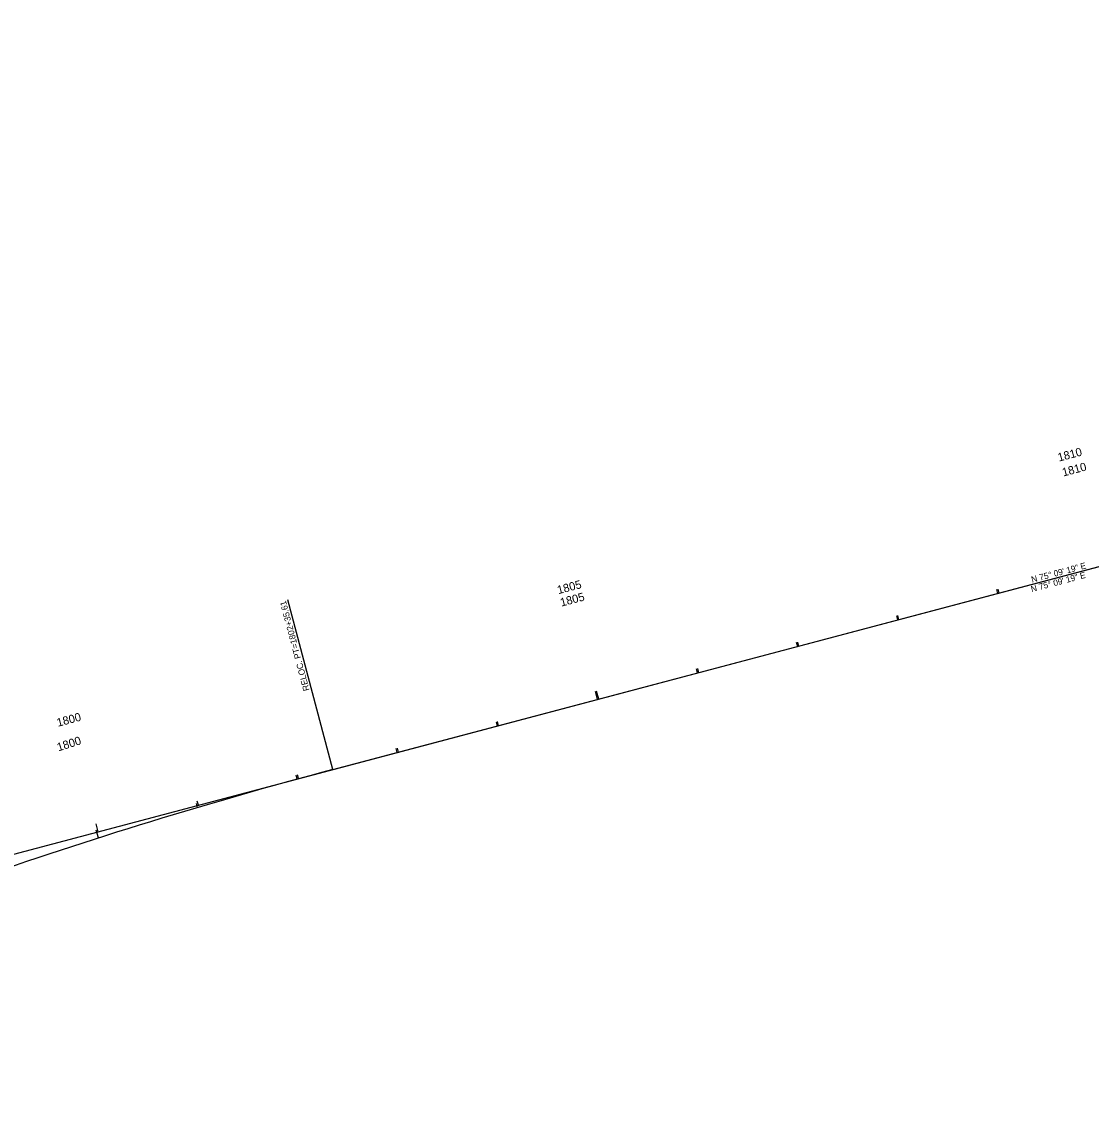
# Model space of a CAD drawing. Extents: x 2106154 to 2121963, y 864504 to 868517.
# Drawn here: x 2111052 to 2112084, y 867153 to 868210 of the extents above; entities that cross this region are included whole.
import ezdxf

# ---------------------------------------------------------------- set-up
doc = ezdxf.new("R2010")
doc.units = 0
for name, color, linetype in [('RD_HC_CL_Rel', 7, 'Continuous'), ('RD_HC_Data_Tic_Rel', 7, 'Continuous'), ('RD_HC_TX_Rel_Sta50', 7, 'Continuous'), ('RD_PD_EarthShd', 7, 'Continuous'), ('RD_PD_EOP', 7, 'Continuous'), ('RD_PD_Final_LnLine', 7, 'Continuous'), ('RD_Sketch1', 7, 'Continuous'), ('RD_Sketch10', 7, 'Continuous')]:
    doc.layers.add(name, color=color, linetype=linetype)

msp = doc.modelspace()

# ---------------------------------------------------------------- linework, layer by layer
at = {"layer": 'RD_HC_Data_Tic_Rel'}
msp.add_line((2111352, 867487.6), (2112776.4, 867865.1), dxfattribs=at)
msp.add_arc((2112556.1, 862944.4), 4700, 104.8448, 109.3083, dxfattribs=at)
at = {"layer": 'RD_HC_TX_Rel_Sta50'}
msp.add_line((2111352, 867487.6), (2111308.5, 867651.6), dxfattribs=at)
at = {"layer": 'RD_PD_EarthShd'}
for p, q in [((2111995.4, 867658.1), (2111994.4, 867662)), ((2111898.7, 867632.5), (2111897.7, 867636.3)), ((2111802.1, 867606.9), (2111801.1, 867610.7)), ((2111705.4, 867581.2), (2111704.4, 867585.1)), ((2111608.8, 867555.6), (2111606.7, 867563.4)), ((2111512.1, 867530), (2111511.1, 867533.9)), ((2111415.4, 867504.4), (2111414.4, 867508.2)), ((2111318.8, 867478.8), (2111317.7, 867482.6)), ((2111222.1, 867453.1), (2111221.1, 867457)), ((2111125.4, 867427.5), (2111123.4, 867435.3))]:
    msp.add_line(p, q, dxfattribs=at)
at = {"layer": 'RD_PD_EOP'}
msp.add_line((2110088.7, 867152.7), (2114077.7, 868210), dxfattribs=at)
at = {"layer": 'RD_Sketch1'}
for p, q in [((2111994.2, 867657.8), (2111993.2, 867661.6)), ((2111897.5, 867632.2), (2111896.5, 867636)), ((2111800.9, 867606.5), (2111799.8, 867610.4)), ((2111704.2, 867580.9), (2111703.2, 867584.8)), ((2111607.5, 867555.3), (2111605.5, 867563)), ((2111510.9, 867529.7), (2111509.9, 867533.5)), ((2111414.2, 867504.1), (2111413.2, 867507.9)), ((2111317.6, 867478.3), (2111316.5, 867482.2)), ((2111221.4, 867450.9), (2111220.3, 867454.8)), ((2111125.8, 867421.5), (2111123.4, 867429.1))]:
    msp.add_line(p, q, dxfattribs=at)

# ---------------------------------------------------------------- texts
at = {"layer": 'RD_HC_CL_Rel'}
msp.add_text('N 75%%d 09\' 19" E', height=6, rotation=14.8448, dxfattribs=at).set_placement((2112027.3, 867668.1))
at = {"layer": 'RD_HC_TX_Rel_Sta50'}
for s, rotation, p in [('N 75%%d 09\' 19" E', 14.8448, (2112026.9, 867659)), ('RELOC. PT=1802+35.61', 104.8448, (2111329.5, 867564.4))]:
    msp.add_text(s, height=6, rotation=rotation, dxfattribs=at).set_placement(p)
at = {"layer": 'RD_PD_Final_LnLine'}
for s, p in [('1810', (2112053.1, 867785.1)), ('1805', (2111569.8, 867657)), ('1800', (2111086.5, 867528.9))]:
    msp.add_text(s, height=8, rotation=14.8448, dxfattribs=at).set_placement(p)
at = {"layer": 'RD_Sketch10'}
for s, rotation, p in [('1810', 14.8448, (2112057.4, 867770.7)), ('1805', 14.8448, (2111572.7, 867645)), ('1800', 17.7171, (2111087, 867505.1))]:
    msp.add_text(s, height=8, rotation=rotation, dxfattribs=at).set_placement(p)

doc.saveas('drawing.dxf')
